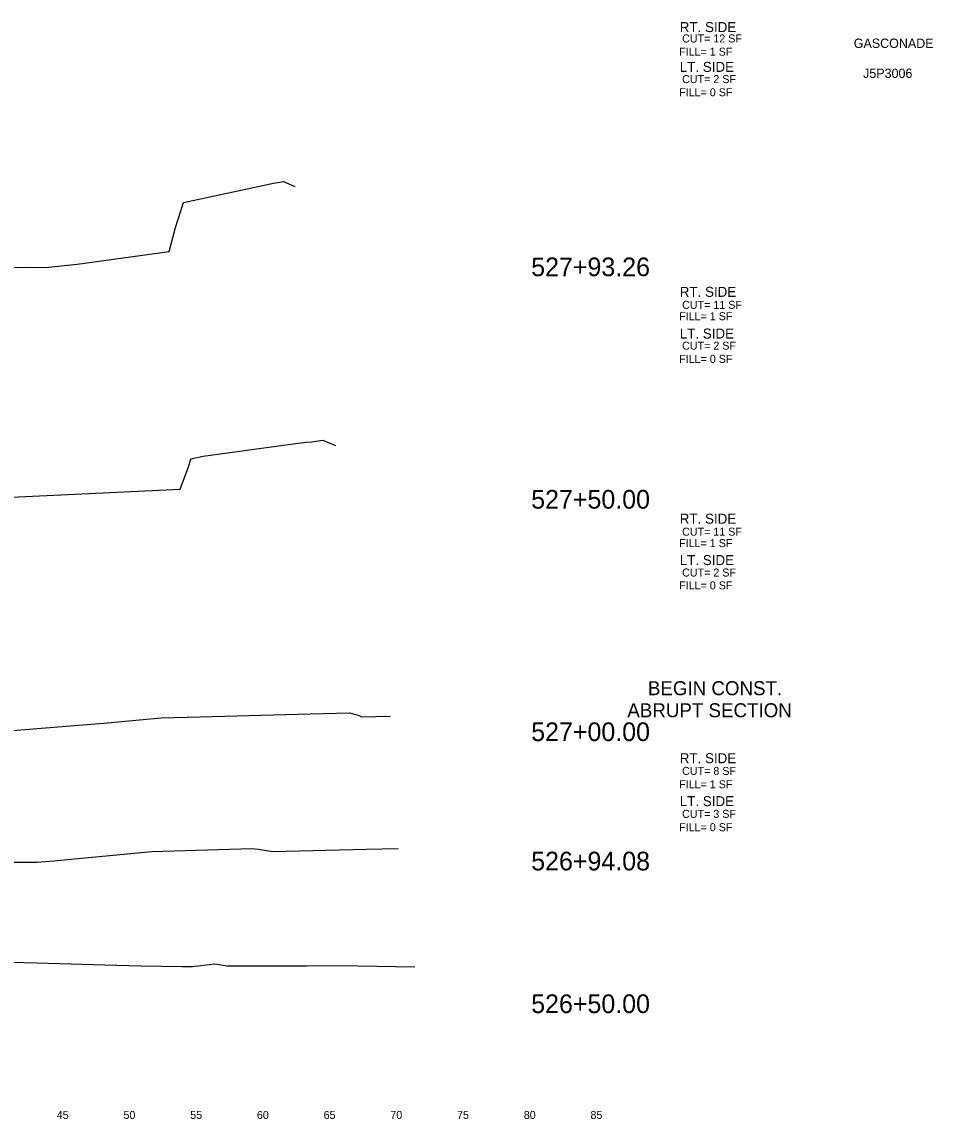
# Model space of a CAD drawing. Extents: x -4 to 359, y 0 to 1436.
# Drawn here: x 85.9 to 154.2, y 0.5 to 82.7 of the extents above; entities that cross this region are included whole.
import ezdxf

# ---------------------------------------------------------------- set-up
doc = ezdxf.new("R2010")
doc.units = 0
for name, color, linetype in [('Common-Title block info', 7, 'Continuous'), ('XS-Existing surface-ground', 7, 'Continuous'), ('XS-Text-earthwork labels', 7, 'Continuous'), ('XS-Text-offset label', 7, 'Continuous'), ('XS-Text-pavement elevation', 7, 'Continuous')]:
    doc.layers.add(name, color=color, linetype=linetype)

msp = doc.modelspace()

# ---------------------------------------------------------------- linework, layer by layer
at = {"layer": 'XS-Existing surface-ground'}
for p, q in [((104.718, 70.671), (105.486, 70.776)), ((105.486, 70.776), (106.332, 70.409)), ((97.972, 69.215), (104.718, 70.671)), ((97.386, 67.347), (97.972, 69.215)), ((96.896, 65.543), (97.386, 67.347)), ((90.001, 64.59), (96.896, 65.543)), ((84.621, 64.351), (86.235, 64.345)), ((86.235, 64.345), (87.857, 64.374)), ((87.857, 64.374), (90.001, 64.59)), ((99.467, 50.196), (106.38, 51.141)), ((106.38, 51.141), (107.194, 51.238)), ((107.194, 51.238), (107.576, 51.278)), ((107.576, 51.278), (108.412, 51.383)), ((108.412, 51.383), (109.378, 50.988)), ((98.537, 49.995), (99.467, 50.196)), ((97.741, 47.714), (98.346, 49.387)), ((98.346, 49.387), (98.537, 49.995)), ((82.608, 46.994), (97.741, 47.714)), ((92.286, 30.2), (96.295, 30.566)), ((96.295, 30.566), (99.236, 30.656)), ((99.236, 30.656), (107.475, 30.866)), ((107.475, 30.866), (110.436, 30.951)), ((110.436, 30.951), (111.135, 30.743)), ((111.135, 30.743), (111.321, 30.651)), ((111.321, 30.651), (113.472, 30.709)), ((85.17, 29.632), (92.286, 30.2)), ((95.599, 20.542), (103.091, 20.771)), ((103.091, 20.771), (103.581, 20.725)), ((103.581, 20.725), (104.677, 20.543)), ((104.677, 20.543), (111.68, 20.72)), ((111.68, 20.72), (114.06, 20.785)), ((84.818, 19.744), (87.004, 19.746)), ((87.004, 19.746), (88.27, 19.844)), ((88.27, 19.844), (89.816, 20.014)), ((89.816, 20.014), (95.599, 20.542)), ((82.402, 12.338), (86.991, 12.193)), ((86.991, 12.193), (92.086, 12.063)), ((92.086, 12.063), (94.775, 11.989)), ((94.775, 11.989), (97.885, 11.922)), ((97.885, 11.922), (98.664, 11.934)), ((98.664, 11.934), (100.325, 12.127)), ((100.325, 12.127), (101.225, 11.971)), ((101.225, 11.971), (103.616, 11.979)), ((103.616, 11.979), (107.243, 11.983)), ((107.243, 11.983), (109.626, 12)), ((109.626, 12), (115.329, 11.896))]:
    msp.add_line(p, q, dxfattribs=at)

# ---------------------------------------------------------------- texts
at = {"layer": 'Common-Title block info'}
for s, p in [('GASCONADE', (148.211, 80.801)), ('J5P3006', (148.909, 78.551))]:
    msp.add_text(s, height=0.7, dxfattribs=at).set_placement(p)
at = {"layer": 'XS-Text-earthwork labels'}
for s, height, p in [('RT. SIDE', 0.75, (135.171, 81.988)), (' CUT= 12 SF           ', 0.6, (135.125, 81.209)), ('FILL= 1 SF           ', 0.6, (135.125, 80.221)), ('LT. SIDE', 0.75, (135.171, 79.005)), (' CUT= 2 SF           ', 0.6, (135.125, 78.164)), ('FILL= 0 SF           ', 0.6, (135.125, 77.176)), ('RT. SIDE', 0.75, (135.171, 62.138)), (' CUT= 11 SF           ', 0.6, (135.125, 61.238)), ('FILL= 1 SF           ', 0.6, (135.125, 60.386)), ('LT. SIDE', 0.75, (135.171, 59.011)), (' CUT= 2 SF           ', 0.6, (135.125, 58.178)), ('FILL= 0 SF           ', 0.6, (135.125, 57.188)), ('RT. SIDE', 0.75, (135.171, 45.128)), (' CUT= 11 SF           ', 0.6, (135.125, 44.23)), ('FILL= 1 SF           ', 0.6, (135.125, 43.372)), ('LT. SIDE', 0.75, (135.171, 42.026)), (' CUT= 2 SF           ', 0.6, (135.125, 41.169)), ('FILL= 0 SF           ', 0.6, (135.125, 40.205)), ('RT. SIDE', 0.75, (135.171, 27.171)), (' CUT= 8 SF           ', 0.6, (135.125, 26.294)), ('FILL= 1 SF           ', 0.6, (135.125, 25.292)), ('LT. SIDE', 0.75, (135.171, 23.952)), (' CUT= 3 SF           ', 0.6, (135.125, 23.075)), ('FILL= 0 SF           ', 0.6, (135.125, 22.073))]:
    msp.add_text(s, height=height, dxfattribs=at).set_placement(p)
at = {"layer": 'XS-Text-offset label'}
for s, height, p in [('           527+93.26           ', 1.4, (118.317, 63.686)), ('           527+50.00           ', 1.4, (118.317, 46.259)), ('           527+00.00           ', 1.4, (118.317, 28.83)), ('           526+94.08           ', 1.4, (118.317, 19.135)), ('           526+50.00           ', 1.4, (118.317, 8.437)), ('           45           ', 0.6, (86.03, 0.5)), ('           50           ', 0.6, (91.03, 0.5)), ('           55           ', 0.6, (96.03, 0.5)), ('           60           ', 0.6, (101.03, 0.5)), ('           65           ', 0.6, (106.03, 0.5)), ('           70           ', 0.6, (111.03, 0.5)), ('           75           ', 0.6, (116.03, 0.5)), ('           80           ', 0.6, (121.03, 0.5)), ('           85           ', 0.6, (126.03, 0.5))]:
    msp.add_text(s, height=height, dxfattribs=at).set_placement(p)
at = {"layer": 'XS-Text-pavement elevation'}
for s, p in [('BEGIN CONST.', (132.783, 32.272)), ('ABRUPT SECTION', (131.241, 30.616))]:
    msp.add_text(s, height=1.05, dxfattribs=at).set_placement(p)

doc.saveas('drawing.dxf')
